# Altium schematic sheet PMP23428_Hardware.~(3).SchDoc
size 431 x 279 mm; Date: Not shown in title block; ApprovedBy: Not shown in title block; CheckedBy: Not shown in title block; Author: Not shown in title block; CompanyName: Not shown in title block; Engineer: Not shown in title block; Organization: Not shown in title block; Address1: Not shown in title block; Address2: Not shown in title block; Address3: Not shown in title block; Address4: Not shown in title block; DocumentNumber: 3; Revision: Use project parameter SCH_Rev; SheetNumber: 4; SheetTotal: 4; PageSetup: Record=PageOptions¦CenterHorizontal=True¦CenterVertical=True¦PrintScale=1.00¦XCorrection=1.00¦YCorrection=1.00¦PrintKind=0¦BorderSize=5000000¦LeftOffset=0¦BottomOffset=0¦Orientation=2¦PaperLength=1000¦PaperWidth=1000¦Scale=100¦PaperSource=15¦PrintQuality=600¦MediaType=1¦DitherType=10¦PaperKind=Letter¦PrintScaleMode=1
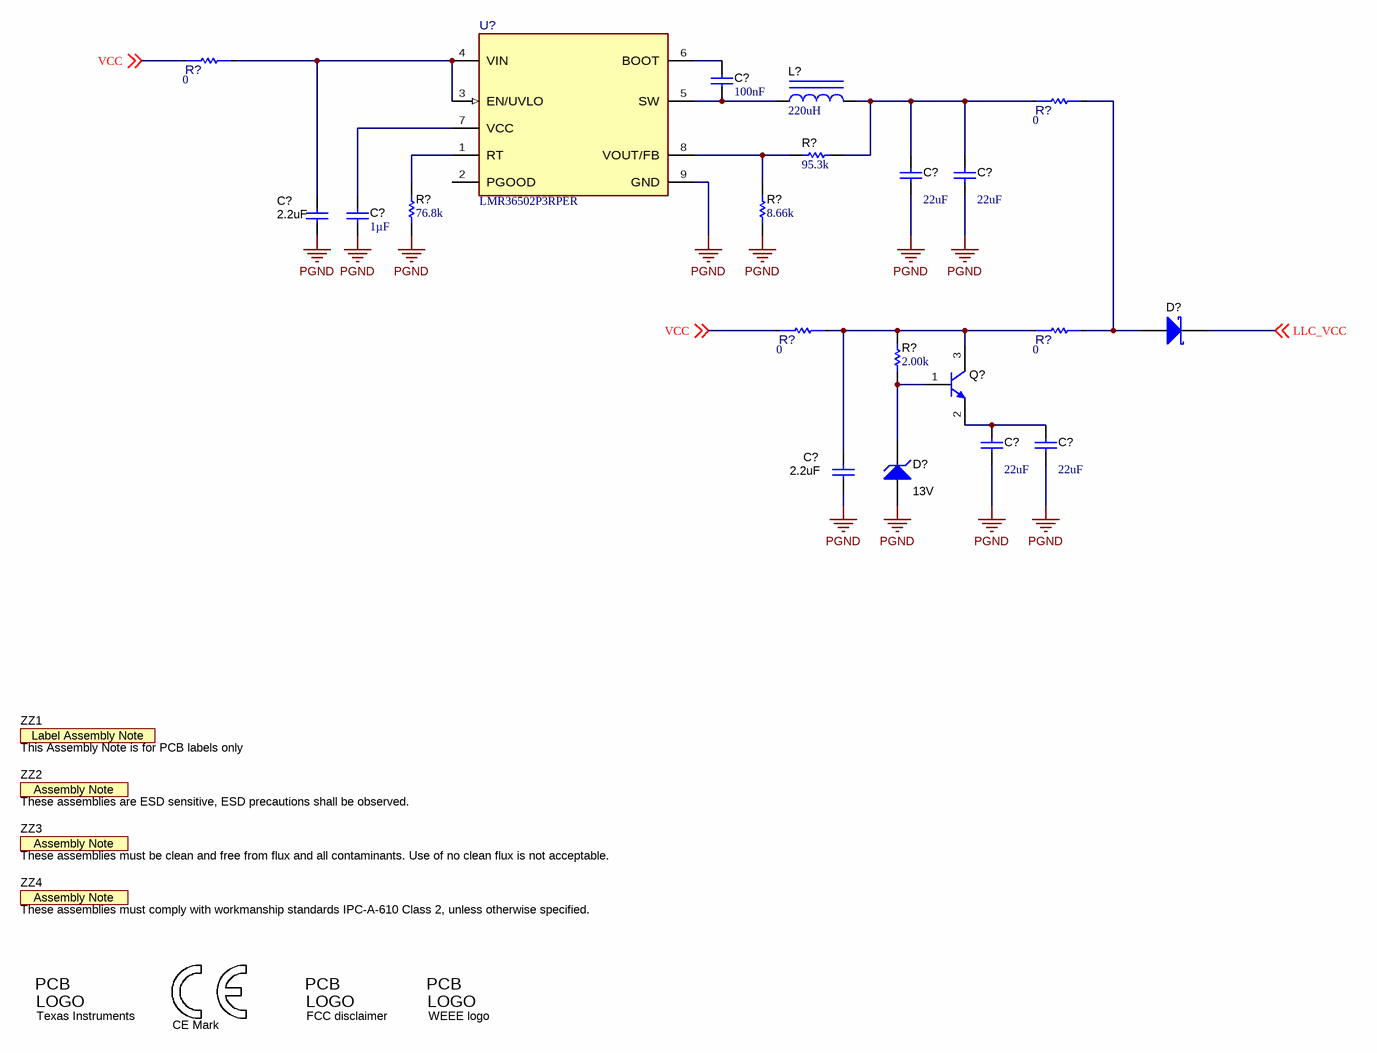
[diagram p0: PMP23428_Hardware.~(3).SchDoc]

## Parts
(Parts that share a designator on the sheet are numbered #1, #2 ... from top to bottom, then left to right.)
C?#1  Cap_F: 100nF  [0603]  (hidden comment: C0603X104K3RACTU)
C?#2  ValueDisplayed: 22uF  [1210_270]  (hidden comment: GRM32ER61E226KE15L)
C?#3  ValueDisplayed: 22uF  [1210_270]  (hidden comment: GRM32ER61E226KE15L)
C?#4  ValueDisplayed: 2.2uF  [0805L]  (hidden comment: C2012X7R1V225K085AC)
C?#5  Cap_F: 1µF  [0603]  (hidden comment: C1608X7R1V105K080AC)
C?#6  ValueDisplayed: 22uF  [1210_270]  (hidden comment: GRM32ER61E226KE15L)
C?#7  ValueDisplayed: 22uF  [1210_270]  (hidden comment: GRM32ER61E226KE15L)
C?#8  ValueDisplayed: 2.2uF  [0805L]  (hidden comment: C2012X7R1V225K085AC)
D?#1  BAT54WS-7-F  [SOD-323]  (value not drawn)
D?#2  value 13V  [SOD-123]  (hidden comment: MMSZ5243B-7-F)
L?  ValueDisplayed: 220uH  [MSS5121]  (hidden comment: MSS5121-224MLB)
Logo1  CE Mark  [CE_Mark_5mm]  (no BOM)
Logo2  Texas Instruments  [TI_Stacked_Overlay_Small]  (no BOM)
Logo3  FCC disclaimer  [FCC_disclaimer]  (no BOM)
Logo4  WEEE logo  [WEEE_Minimum]  (no BOM)
Q?  MMBTA05LT1G  [SOT-23]  (value not drawn)
R?#1  value 0  [FP-RMCF1206ZT0R00_1206-MFG]  (hidden comment: RMCF1206ZT0R00)
R?#2  value 0  [FP-RMCF1206ZT0R00_1206-MFG]  (hidden comment: RMCF1206ZT0R00)
R?#3  ValueDisplayed: 95.3k  [0603]  (hidden comment: RC0603FR-0795K3L)
R?#4  ValueDisplayed: 76.8k  [0603]  (hidden comment: RC0603FR-0776K8L)
R?#5  ValueDisplayed: 8.66k  [0603]  (hidden comment: RC0603FR-078K66L)
R?#6  value 0  [FP-RMCF1206ZT0R00_1206-MFG]  (hidden comment: RMCF1206ZT0R00)
R?#7  value 0  [FP-RMCF1206ZT0R00_1206-MFG]  (hidden comment: RMCF1206ZT0R00)
R?#8  ValueDisplayed: 2.00k  [0603]  (hidden comment: RC0603FR-072KL)
U?  LMR36502P3RPER  [RPE0009B-MFG]
ZZ1  This Assembly Note is for PCB labels only  [AssemblyNoteLabel]  (no BOM)
ZZ2  These assemblies are ESD sensitive, ESD precautions shall be observed.  [AssemblyNote]  (no BOM)
ZZ3  These assemblies must be clean and free from flux and all contaminants. Use of no clean flux is not acceptable.  [AssemblyNote]  (no BOM)
ZZ4  These assemblies must comply with workmanship standards IPC-A-610 Class 2, unless otherwise specified.  [AssemblyNote]  (no BOM)

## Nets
PGND: C?#2.2 C?#3.2 C?#4.2 C?#5.2 C?#6.2 C?#7.2 C?#8.2 D?#2.2(A) R?#4.1 R?#5.1 U?.9(GND)
LLC_VCC: D?#1.1(K) ; off-sheet LLC_VCC
VCC: R?#1.1 R?#6.1 ; off-sheet VCC
NetC?#1_1: C?#1.1 U?.6(BOOT)
NetC?#1_2: C?#1.2 L?.1 U?.5(SW)
NetC?#2_1: C?#2.1 C?#3.1 L?.2 R?#2.1 R?#3.1
NetC?#4_1: C?#4.1 R?#1.2 U?.3(EN/UVLO) U?.4(VIN)
NetC?#5_1: C?#5.1 U?.7(VCC)
NetC?#6_1: C?#6.1 C?#7.1 Q?.2(E)
NetC?#8_1: C?#8.1 Q?.3(C) R?#6.2 R?#7.1 R?#8.2
NetD?#1_2: D?#1.2(A) R?#2.2 R?#7.2
NetD?#2_1: D?#2.1(K) Q?.1(B) R?#8.1
NetR?#3_2: R?#3.2 R?#5.2 U?.8(VOUT/FB)
NetR?#4_2: R?#4.2 U?.1(RT)

Not connected (* = marked no-connect by the designer): U? 2(PGOOD)

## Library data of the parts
C?#1 = CMP-0006979-5: CAP, CERM, 0.1 uF, 25 V, +/- 10%, X7R, 0603; Manufacturer: Kemet; TaMin_C: -55°C; Polarized: N; SizeAreaWB_mm2: 4.68; Value1: Unknown; U/M: EA; Value: 0.1uF; TaMax_C: 125°C; SizeZ_mm: 1; SizeX_mm: 1.6; SizeY_mm: 0.8; Value2: 25V; SizeArea_mm2: 1.28; AEC Category: Q200
C?#2 C?#3 C?#6 C?#7 = CMP-0009213-2: CAP, CERM, 22 uF, 25 V, +/- 10%, X5R, 1210; Manufacturer: MuRata; TaMin_C: -55°C; ESR_ohm: 2m; Polarized: N; SizeAreaWB_mm2: 14.7; Value1: 0.002 ohm; U/M: EA; Value: 22uF; TaMax_C: 85°C; SizeZ_mm: 2.7; SizeX_mm: 3.2; SizeY_mm: 2.5; Cap_Case: 1210; Value2: 25V; SizeArea_mm2: 8; Cap_F: 22µF; IRMS_A: 3.67A; AEC Category: Q200
C?#4 C?#8 = CMP-0007883-2: CAP, CERM, 2.2 uF, 35 V, +/- 10%, X7R, 0805; Manufacturer: TDK; TaMin_C: -55°C; Polarized: N; SizeAreaWB_mm2: 6.75; Value1: Unknown; U/M: EA; Value: 2.2uF; TaMax_C: 125°C; SizeZ_mm: 1.45; SizeX_mm: 2; SizeY_mm: 1.25; Cap_Case: 0805; Value2: 35V; SizeArea_mm2: 2.5; CompType: Capacitor; Cap_F: 2.2µF; AEC Category: Q200
C?#5 = CMP-0007052-4: CAP, CERM, 1 uF, 35 V, +/- 10%, X7R, 0603; Manufacturer: TDK; TaMin_C: -55°C; Polarized: N; SizeAreaWB_mm2: 4.68; Value1: Unknown; U/M: EA; Value: 1uF; TaMax_C: 125°C; SizeZ_mm: 1; SizeX_mm: 1.6; SizeY_mm: 0.8; Value2: 35V; SizeArea_mm2: 1.28; AEC Category: Q200
D?#1 = CMP-0028458-2: Diode, Schottky, 30 V, 0.2 A, SOD-323; Manufacturer: Diodes Inc.; SizeArea_mm2: 3.645; Green_Lifecycle: Active; Io_A: 200mA; TJmax_C: 125°C; Value2: 0.7V; Vf_V: 700mV; Green_REACh: Passed; Value1: 0.2A; Vr_V: 30V; AEC Category: Q101; SizeAreaWB_mm2: 8.695; SizeY_mm: 1.35; Value: 30V; SizeX_mm: 2.7; SizeZ_mm: 1
D?#2 = CMP-0005752-4: Diode, Zener, 13 V, 500 mW, SOD-123; Manufacturer: Diodes Inc.; Value1: 0.5W; SizeAreaWB_mm2: 13.095; RJA_CperW: 350; AEC Category: Q101; SizeZ_mm: 1.35; SizeX_mm: 3.85; Power_W: 500mW; SizeArea_mm2: 6.545; SizeY_mm: 1.7
L? = CMP-0061952-2: Inductor, Shielded Drum Core, Ferrite, 220 uH, 0.25 A, 3.1 ohm, SMD; Manufacturer: Coilcraft; Isat: 0.25A @ 30% inductance drop; Irms: 0.29A @ 40C rise; Green_Lifecycle: Not Set; SizeAreaWB_mm2: 54.76; DCR_ohm: 3.1; Green_REACh: Incomplete; Value1: 3.1 ohm; Value: 220uH; Imax_A: 2.5dA; SizeZ_mm: 2.2; SizeX_mm: 5.4; Value2: 0.25A; SizeArea_mm2: 29.16; Ind_H: 220µH; AEC Category: Q200
Logo1 = CMP-0074844-1: SymbolCreator: a0412235
Logo2 = CMP-0074838-1: Texas Instrument Corporate Signature; SymbolCreator: a0412235; Lib Reference: TI_Logo; Library Reference: Logo
Logo3 = CMP-0074847-1: FCC_disclaimer; Library Reference: Logo
Logo4 = CMP-0074769-1
Q? = CMP-0000488-2: Transistor, NPN, 60 V, 0.5 A, AEC-Q101, SOT-23; Manufacturer: ON Semiconductor; TaMax_C: 150°C; Value1: 0.5 A; Vcesat1_V: 2.5dV; SizeX_mm: 2.5; SizeY_mm: 3; TaMin_C: -55°C; IcRated_A: 5dA; CompType: BJT; SizeZ_mm: 1.1; AEC Qualified: Y; Value: 60 V; SizeArea_mm2: 7.5; NPN: 1; Vceo_V: 60V; PNP: 0; AEC Category: Q101; SizeAreaWB_mm2: 14; U/M: EA
R?#1 R?#2 R?#6 R?#7 = CMP-0093609-1: 0Ω ±0 0.25W 1206 Thick Film Chip Resistor AEC-Q200 compliant; Manufacturer: Stackpole Electronics; AEC Qualified: Yes; VDC_V: 200V; AEC Grade: Grade 0; Power_W: 250mW; SizeZ_mm: 0.7mm
R?#3 = CMP-0023326-5: RES, 95.3 k, 1%, 0.1 W, 0603; Manufacturer: Yageo; Power_W: 100mW; TempCo: 100 ppm/C; Value_Code: 95k3; Value: 95.3k; EIA_Code: E96; SizeX_mm: 1.6; SizeY_mm: 0.8; SizeZ_mm: 1; Value2: 0.1W; SizeArea_mm2: 1.28; AEC Qualified: N; VDC_V: 75V; AEC Category: Q200; SizeAreaWB_mm2: 4.68
R?#4 = CMP-0023271-5: RES, 76.8 k, 1%, 0.1 W, 0603; Manufacturer: Yageo; Power_W: 100mW; TempCo: 100 ppm/C; Value_Code: 76k8; Value: 76.8k; EIA_Code: E96; SizeX_mm: 1.6; SizeY_mm: 0.8; SizeZ_mm: 1; Value2: 0.1W; SizeArea_mm2: 1.28; AEC Qualified: N; VDC_V: 75V; AEC Category: Q200; SizeAreaWB_mm2: 4.68
R?#5 = CMP-0023310-5: RES, 8.66 k, 1%, 0.1 W, 0603; Manufacturer: Yageo; Power_W: 100mW; TempCo: 100 ppm/C; Value_Code: 8k66; Value: 8.66k; EIA_Code: E96; SizeX_mm: 1.6; SizeY_mm: 0.8; SizeZ_mm: 1; Value2: 0.1W; SizeArea_mm2: 1.28; AEC Qualified: N; VDC_V: 75V; AEC Category: Q200; SizeAreaWB_mm2: 4.68
R?#8 = CMP-0023000-5: RES, 2.00 k, 1%, 0.1 W, 0603; Manufacturer: Yageo; Power_W: 100mW; TempCo: 100 ppm/C; Value_Code: 2k00; Value: 2.00k; EIA_Code: E96; Res_ohm: 2k; SizeX_mm: 1.6; SizeY_mm: 0.8; SizeZ_mm: 1; Value2: 0.1W; SizeArea_mm2: 1.28; AEC Qualified: N; VDC_V: 75V; AEC Category: Q200; SizeAreaWB_mm2: 4.68
U? = CMP-0120075-1: 3-V to 65-V, 150-mA Wide VIN Synchronous Buck Converter Optimized for Size and Light Load Efficiency; Manufacturer: Texas Instruments; SizeZ_mm: 1mm; AEC Qualified: No; Max Duty Cycle: 98%; Max Supply Voltage: 65V; Min Supply Voltage: 3.6V; Nominal Supply Current: 0.672-18uA; Number Of Outputs: 1; Output Type: Fixed,AdjustableProgrammable; Output Voltage: 3.3/1-16V; Standoff Height: 0mm; Switching Frequency: 0.2-2.2MHz; TJmax_C: +150°C
ZZ1 = CMP-0003616-3
ZZ2 = CMP-0077236-1
ZZ3 = CMP-0077237-1
ZZ4 = CMP-0077238-1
